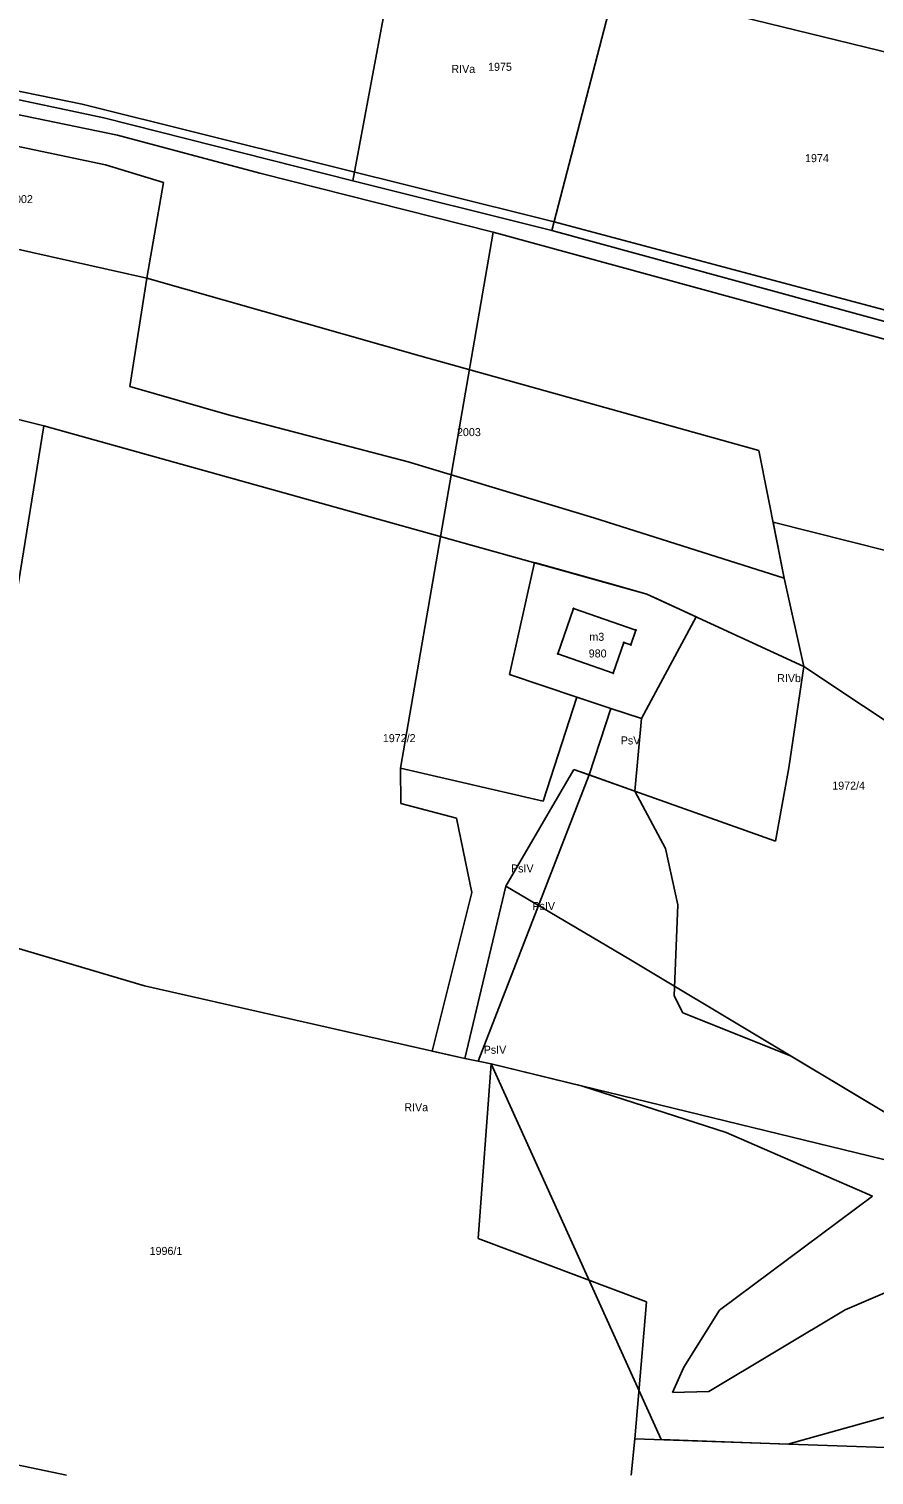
# Model space of a CAD drawing. Extents: x 7498273 to 7499989, y 5499795 to 5500810.
# Drawn here: x 7499281.1 to 7499439.5, y 5499795 to 5500066 of the extents above; entities that cross this region are included whole.
import ezdxf

# ---------------------------------------------------------------- set-up
doc = ezdxf.new("R2010")
doc.units = 0
for name, color, linetype in [('209-oznaczenie konturu klasyfikacyjnego', 7, 'Continuous'), ('211-numer działki ewidencyjnej', 7, 'Continuous'), ('217-kontur klasyfikacyjny', 7, 'Continuous'), ('218-kontur użytku gruntowego', 7, 'Continuous'), ('219-działka ewidencyjna', 7, 'Continuous'), ('312-budynek ewidencyjny', 7, 'Continuous'), ('312-oznaczenie budynku ewidencyjnego', 7, 'Continuous'), ('312-oznaczenie budynku ewidencyjnego-Atr117', 7, 'Continuous'), ('Punkt budynku', 7, 'Continuous')]:
    doc.layers.add(name, color=color, linetype=linetype)

# ---------------------------------------------------------------- blocks, each defined once
blk = doc.blocks.new('PUNKTBUD')
blk.add_circle((0, 0), 0.09)

msp = doc.modelspace()

# ---------------------------------------------------------------- linework, layer by layer
at = {"layer": '217-kontur klasyfikacyjny'}
for points in [[(7499450.96, 5500059.44), (7499391.03, 5500074.12)], [(7499246.69, 5500061), (7499291.1, 5500051.95)], [(7499297.7, 5500046.12), (7499247.42, 5500056.48)], [(7499291.1, 5500051.95), (7499379.58, 5500029.9)], [(7499324.36, 5500039.03), (7499297.7, 5500046.12)], [(7499368.14, 5500027.95), (7499324.36, 5500039.03)], [(7499350.76, 5499927.52), (7499368.14, 5500027.95)], [(7499368.14, 5500027.95), (7499482.6, 5499996.67)], [(7499379.58, 5500029.9), (7499463.91, 5500007.39)], [(7499420.59, 5499973.59), (7499422.66, 5499963.09)], [(7499456.78, 5499964.49), (7499420.59, 5499973.59)], [(7499371.16, 5499945.07), (7499375.84, 5499966.02)], [(7499375.84, 5499966.02), (7499390.61, 5499961.9)], [(7499422.66, 5499963.09), (7499426.37, 5499946.58)], [(7499390.61, 5499961.9), (7499396.94, 5499960.13)], [(7499396.94, 5499960.13), (7499398.89, 5499959.23)], [(7499398.89, 5499959.23), (7499406.18, 5499955.88)], [(7499406.18, 5499955.88), (7499395.95, 5499936.82)], [(7499426.37, 5499946.58), (7499448.74, 5499931.67)], [(7499383.8, 5499940.82), (7499371.16, 5499945.07)], [(7499383.8, 5499940.82), (7499377.5, 5499921.33)], [(7499390.15, 5499938.68), (7499383.8, 5499940.82)], [(7499386.12, 5499926.26), (7499390.15, 5499938.68)], [(7499395.95, 5499936.82), (7499390.15, 5499938.68)], [(7499394.7, 5499923.21), (7499395.95, 5499936.82)], [(7499350.83, 5499920.9), (7499350.76, 5499927.52)], [(7499377.5, 5499921.33), (7499350.76, 5499927.52)], [(7499370.51, 5499905.37), (7499383.27, 5499927.27)], [(7499383.27, 5499927.27), (7499386.12, 5499926.26)], [(7499365.34, 5499872.57), (7499386.12, 5499926.26)], [(7499394.7, 5499923.21), (7499386.12, 5499926.26)], [(7499400.45, 5499912.47), (7499394.7, 5499923.21)], [(7499361.25, 5499918.14), (7499350.83, 5499920.9)], [(7499364.14, 5499904.17), (7499361.25, 5499918.14)], [(7499402.73, 5499901.91), (7499400.45, 5499912.47)], [(7499356.67, 5499874.48), (7499364.14, 5499904.17)], [(7499362.83, 5499873.09), (7499370.51, 5499905.37)], [(7499402.05, 5499884.81), (7499402.73, 5499901.91)], [(7499403.69, 5499881.68), (7499402.05, 5499884.81)], [(7499423.87, 5499873.6), (7499403.69, 5499881.68)], [(7499362.83, 5499873.09), (7499356.67, 5499874.48)], [(7499365.34, 5499872.57), (7499362.83, 5499873.09)], [(7499444.1, 5499861.48), (7499423.87, 5499873.6)], [(7499367.74, 5499872.11), (7499365.34, 5499872.57)], [(7499399.59, 5499801.67), (7499367.74, 5499872.11)], [(7499367.74, 5499872.11), (7499384.89, 5499867.93)], [(7499384.89, 5499867.93), (7499411.83, 5499859.25)], [(7499411.83, 5499859.25), (7499439.21, 5499847.32)], [(7499439.21, 5499847.32), (7499410.54, 5499825.95)], [(7499434.12, 5499826), (7499478.68, 5499845.08)], [(7499410.54, 5499825.95), (7499403.86, 5499815.26)], [(7499408.53, 5499810.68), (7499434.12, 5499826)], [(7499493.48, 5499820.35), (7499423.34, 5499800.83)], [(7499403.86, 5499815.26), (7499401.77, 5499810.48)], [(7499401.77, 5499810.48), (7499408.53, 5499810.68)], [(7499288.164, 5499795.022), (7499243.91, 5499804.22)], [(7499423.34, 5499800.83), (7499399.59, 5499801.67)]]:
    msp.add_lwpolyline(points, dxfattribs=at)
at = {"layer": '218-kontur użytku gruntowego'}
for points in [[(7499450.96, 5500059.44), (7499391.03, 5500074.12)], [(7499246.69, 5500061), (7499291.1, 5500051.95)], [(7499247.42, 5500056.48), (7499297.7, 5500046.12)], [(7499291.1, 5500051.95), (7499379.58, 5500029.9)], [(7499297.7, 5500046.12), (7499324.36, 5500039.03)], [(7499324.36, 5500039.03), (7499368.14, 5500027.95)], [(7499350.76, 5499927.52), (7499368.14, 5500027.95)], [(7499368.14, 5500027.95), (7499482.6, 5499996.67)], [(7499379.58, 5500029.9), (7499463.91, 5500007.39)], [(7499420.59, 5499973.59), (7499422.66, 5499963.09)], [(7499456.78, 5499964.49), (7499420.59, 5499973.59)], [(7499375.84, 5499966.02), (7499371.16, 5499945.07)], [(7499390.61, 5499961.9), (7499375.84, 5499966.02)], [(7499422.66, 5499963.09), (7499426.37, 5499946.58)], [(7499396.94, 5499960.13), (7499390.61, 5499961.9)], [(7499398.89, 5499959.23), (7499396.94, 5499960.13)], [(7499406.18, 5499955.88), (7499398.89, 5499959.23)], [(7499395.95, 5499936.82), (7499406.18, 5499955.88)], [(7499426.37, 5499946.58), (7499448.74, 5499931.67)], [(7499371.16, 5499945.07), (7499383.8, 5499940.82)], [(7499383.8, 5499940.82), (7499377.5, 5499921.33)], [(7499390.15, 5499938.68), (7499383.8, 5499940.82)], [(7499386.12, 5499926.26), (7499390.15, 5499938.68)], [(7499390.15, 5499938.68), (7499395.95, 5499936.82)], [(7499394.7, 5499923.21), (7499395.95, 5499936.82)], [(7499350.83, 5499920.9), (7499350.76, 5499927.52)], [(7499377.5, 5499921.33), (7499350.76, 5499927.52)], [(7499370.51, 5499905.37), (7499383.27, 5499927.27)], [(7499383.27, 5499927.27), (7499386.12, 5499926.26)], [(7499365.34, 5499872.57), (7499386.12, 5499926.26)], [(7499394.7, 5499923.21), (7499386.12, 5499926.26)], [(7499400.45, 5499912.47), (7499394.7, 5499923.21)], [(7499361.25, 5499918.14), (7499350.83, 5499920.9)], [(7499364.14, 5499904.17), (7499361.25, 5499918.14)], [(7499402.73, 5499901.91), (7499400.45, 5499912.47)], [(7499356.67, 5499874.48), (7499364.14, 5499904.17)], [(7499362.83, 5499873.09), (7499370.51, 5499905.37)], [(7499402.05, 5499884.81), (7499402.73, 5499901.91)], [(7499403.69, 5499881.68), (7499402.05, 5499884.81)], [(7499423.87, 5499873.6), (7499403.69, 5499881.68)], [(7499362.83, 5499873.09), (7499356.67, 5499874.48)], [(7499365.34, 5499872.57), (7499362.83, 5499873.09)], [(7499444.1, 5499861.48), (7499423.87, 5499873.6)], [(7499367.74, 5499872.11), (7499365.34, 5499872.57)], [(7499399.59, 5499801.67), (7499367.74, 5499872.11)], [(7499367.74, 5499872.11), (7499384.89, 5499867.93)], [(7499384.89, 5499867.93), (7499411.83, 5499859.25)], [(7499411.83, 5499859.25), (7499439.21, 5499847.32)], [(7499439.21, 5499847.32), (7499410.54, 5499825.95)], [(7499434.12, 5499826), (7499478.68, 5499845.08)], [(7499410.54, 5499825.95), (7499403.86, 5499815.26)], [(7499408.53, 5499810.68), (7499434.12, 5499826)], [(7499493.48, 5499820.35), (7499423.34, 5499800.83)], [(7499403.86, 5499815.26), (7499401.77, 5499810.48)], [(7499401.77, 5499810.48), (7499408.53, 5499810.68)], [(7499243.91, 5499804.22), (7499288.164, 5499795.022)], [(7499423.34, 5499800.83), (7499399.59, 5499801.67)]]:
    msp.add_lwpolyline(points, dxfattribs=at)
at = {"layer": '219-działka ewidencyjna'}
for points in [[(7499341.79, 5500037.59), (7499351.23, 5500088.12)], [(7499379.15, 5500028.26), (7499392.54, 5500079.96)], [(7499243.19, 5500060.39), (7499295.16, 5500049.36)], [(7499248.43, 5500050.43), (7499295.43, 5500040.59)], [(7499295.16, 5500049.36), (7499341.79, 5500037.59)], [(7499295.43, 5500040.59), (7499306.3, 5500037.28)], [(7499303.18, 5500019.36), (7499306.3, 5500037.28)], [(7499341.79, 5500037.59), (7499379.15, 5500028.26)], [(7499249.35, 5500031.38), (7499303.18, 5500019.36)], [(7499379.15, 5500028.26), (7499461.85, 5500005.63)], [(7499300.02, 5499999.01), (7499303.18, 5500019.36)], [(7499303.18, 5500019.36), (7499354.37, 5500004.79)], [(7499354.37, 5500004.79), (7499417.94, 5499987.04)], [(7499244.27, 5500001.51), (7499283.91, 5499991.66)], [(7499300.02, 5499999.01), (7499318.28, 5499993.78)], [(7499352.21, 5499984.93), (7499318.28, 5499993.78)], [(7499268.5, 5499896.86), (7499283.91, 5499991.66)], [(7499283.91, 5499991.66), (7499396.94, 5499960.13)], [(7499417.94, 5499987.04), (7499422.66, 5499963.09)], [(7499352.21, 5499984.93), (7499386.99, 5499974.42)], [(7499386.99, 5499974.42), (7499422.66, 5499963.09)], [(7499396.94, 5499960.13), (7499426.37, 5499946.58)], [(7499423.58, 5499927.56), (7499426.37, 5499946.58)], [(7499370.51, 5499905.37), (7499383.27, 5499927.27)], [(7499383.27, 5499927.27), (7499421.02, 5499913.84)], [(7499421.02, 5499913.84), (7499423.58, 5499927.56)], [(7499370.51, 5499905.37), (7499362.83, 5499873.09)], [(7499370.51, 5499905.37), (7499393.57, 5499891.75)], [(7499268.5, 5499896.86), (7499302.76, 5499886.68)], [(7499393.57, 5499891.75), (7499444.1, 5499861.48)], [(7499302.76, 5499886.68), (7499362.83, 5499873.09)], [(7499362.83, 5499873.09), (7499365.34, 5499872.57)], [(7499365.33, 5499839.35), (7499367.74, 5499872.11)], [(7499365.34, 5499872.57), (7499367.74, 5499872.11)], [(7499521.93, 5499834.54), (7499367.74, 5499872.11)], [(7499365.33, 5499839.35), (7499396.84, 5499827.48)], [(7499394.65, 5499801.84), (7499396.84, 5499827.48)], [(7499394.002, 5499795.022), (7499394.65, 5499801.84)], [(7499394.65, 5499801.84), (7499454.27, 5499799.74)]]:
    msp.add_lwpolyline(points, dxfattribs=at)
at = {"layer": '312-budynek ewidencyjny'}
for points in [[(7499380.27, 5499948.94), (7499383.2, 5499957.4)], [(7499383.2, 5499957.4), (7499394.86, 5499953.37)], [(7499394.86, 5499953.37), (7499393.96, 5499950.62)], [(7499390.64, 5499945.33), (7499380.27, 5499948.94)], [(7499392.63, 5499951.05), (7499390.64, 5499945.33)], [(7499393.96, 5499950.62), (7499392.63, 5499951.05)]]:
    msp.add_lwpolyline(points, dxfattribs=at)

# ---------------------------------------------------------------- block references
at = {"layer": 'Punkt budynku'}
for p in [(7499383.2, 5499957.4), (7499394.86, 5499953.37), (7499380.27, 5499948.94), (7499392.63, 5499951.05), (7499393.96, 5499950.62), (7499390.64, 5499945.33)]:
    msp.add_blockref('PUNKTBUD', p, dxfattribs=at)

# ---------------------------------------------------------------- texts
at = {"layer": '209-oznaczenie konturu klasyfikacyjnego'}
for s, p in [('RIVa', (7499360.29, 5500057.79)), ('RIVb', (7499421.36, 5499943.63)), ('PsV', (7499392.04, 5499931.95)), ('PsIV', (7499371.46, 5499907.96)), ('PsIV', (7499375.48, 5499900.92)), ('PsIV', (7499366.34, 5499873.98)), ('RIVa', (7499351.47, 5499863.21))]:
    msp.add_text(s, height=1.5, dxfattribs=at).set_placement(p)
at = {"layer": '211-numer działki ewidencyjnej'}
for s, p in [('1975', (7499367.17, 5500058.19)), ('1974', (7499426.59, 5500041.07)), ('2002', (7499277.37, 5500033.4)), ('2003', (7499361.34, 5499989.73)), ('1972/2', (7499347.44, 5499932.38)), ('1972/4', (7499431.69, 5499923.48)), ('1996/1', (7499303.72, 5499836.28))]:
    msp.add_text(s, height=1.5, dxfattribs=at).set_placement(p)
at = {"layer": '312-oznaczenie budynku ewidencyjnego'}
msp.add_text('980', height=1.5, dxfattribs=at).set_placement((7499386.04, 5499948.25))
at = {"layer": '312-oznaczenie budynku ewidencyjnego-Atr117'}
msp.add_text('m3', height=1.5, dxfattribs=at).set_placement((7499386.156, 5499951.37))

doc.saveas('drawing.dxf')
